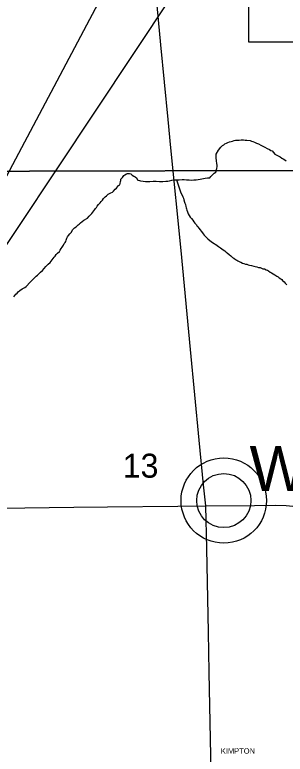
# Model space of a CAD drawing. Extents: x 10.6 to 44.6, y -2.6 to 23.4.
# Drawn here: x 17.431 to 17.902, y 17.784 to 19.074 of the extents above; entities that cross this region are included whole.
import ezdxf

# ---------------------------------------------------------------- set-up
doc = ezdxf.new("R2010")
doc.units = 0
for name, color, linetype in [('GM_X_Minor_River', 7, 'Continuous'), ('GM_X_Section', 7, 'Continuous'), ('GM_X_Section_Text', 7, 'Continuous'), ('GM_X_State_Route', 7, 'Continuous'), ('GM_X_Township_Subdivision_Text', 7, 'Continuous'), ('GM_X_Unincorporated', 7, 'Continuous'), ('GM_X_Unincorporated_Text', 7, 'Continuous'), ('GM_X_US_Route', 7, 'Continuous'), ('SH_Border', 7, 'Continuous')]:
    doc.layers.add(name, color=color, linetype=linetype)

msp = doc.modelspace()

# ---------------------------------------------------------------- linework, layer by layer
at = {"layer": 'GM_X_Minor_River'}
for points in [[(17.7427, 18.7858), (17.7469, 18.7862), (17.7503, 18.7867), (17.7537, 18.7871), (17.7625, 18.7888), (17.7663, 18.7893), (17.7689, 18.7894), (17.7708, 18.7898), (17.7723, 18.7917), (17.7756, 18.7952), (17.7782, 18.7979), (17.7809, 18.7995), (17.783, 18.806), (17.7833, 18.8094), (17.7833, 18.8117), (17.7828, 18.8144), (17.7824, 18.8193), (17.7815, 18.8246), (17.7818, 18.8269), (17.7817, 18.8307), (17.7854, 18.838), (17.7895, 18.843), (17.7924, 18.8457), (17.7947, 18.8473), (17.7969, 18.8489), (17.7996, 18.8501), (17.8022, 18.8513), (17.8049, 18.8521), (17.8075, 18.8529), (17.8098, 18.8537), (17.8132, 18.8545), (17.8154, 18.855), (17.8173, 18.8554), (17.8192, 18.8554), (17.8219, 18.8555), (17.8249, 18.8556), (17.8291, 18.8556), (17.8322, 18.8553), (17.8348, 18.8554), (17.8409, 18.8544), (17.8432, 18.8537), (17.8455, 18.853), (17.8486, 18.8515), (17.8517, 18.8501), (17.8551, 18.8486), (17.8594, 18.8464), (17.8628, 18.8446), (17.8663, 18.8428), (17.8702, 18.8406), (17.8744, 18.8388), (17.8771, 18.8373), (17.879, 18.8366), (17.8837, 18.8306), (17.8894, 18.8277), (17.8929, 18.8259), (17.896, 18.824), (17.8983, 18.8226), (17.901, 18.8207), (17.9037, 18.8193)], [(17.4723, 18.6214), (17.4757, 18.6249), (17.4791, 18.628), (17.482, 18.6315), (17.485, 18.635), (17.4887, 18.6389), (17.4921, 18.6416), (17.4943, 18.6439), (17.4958, 18.6462), (17.4976, 18.6486), (17.4995, 18.6509), (17.501, 18.6528), (17.5028, 18.6559), (17.5054, 18.6579), (17.5084, 18.661), (17.5095, 18.6633), (17.5113, 18.666), (17.5132, 18.6687), (17.5158, 18.6721), (17.5169, 18.6748), (17.5183, 18.6768), (17.5194, 18.6787), (17.5205, 18.681), (17.5216, 18.684), (17.5227, 18.6864), (17.5242, 18.6887), (17.5264, 18.6918), (17.529, 18.6941), (17.5316, 18.6995), (17.5349, 18.7022), (17.5375, 18.7042), (17.5394, 18.7057), (17.5413, 18.7073), (17.5431, 18.7088), (17.5454, 18.7108), (17.548, 18.7131), (17.551, 18.7155), (17.5574, 18.719), (17.5604, 18.7225), (17.5626, 18.7252), (17.5648, 18.7275), (17.5667, 18.7299), (17.5685, 18.7318), (17.5704, 18.7341), (17.5715, 18.7361), (17.573, 18.738), (17.5744, 18.7399), (17.5763, 18.743), (17.5793, 18.7457), (17.5815, 18.7484), (17.5837, 18.7508), (17.5852, 18.7535), (17.5882, 18.7562), (17.5904, 18.7581), (17.5934, 18.7612), (17.5979, 18.7632), (17.6009, 18.7648), (17.6028, 18.766), (17.6058, 18.7695), (17.608, 18.7718), (17.6098, 18.7741), (17.6117, 18.7761), (17.6136, 18.7776), (17.6143, 18.7799), (17.615, 18.783), (17.6157, 18.7849), (17.6157, 18.7872), (17.6186, 18.7903), (17.6209, 18.7934), (17.6227, 18.7946), (17.6253, 18.7965), (17.6272, 18.7969), (17.6307, 18.797), (17.633, 18.7967), (17.6353, 18.7944), (17.638, 18.7926), (17.6407, 18.7911), (17.6434, 18.7889), (17.6442, 18.7863), (17.6496, 18.7845), (17.6542, 18.7835), (17.6583, 18.7832), (17.6621, 18.7832), (17.666, 18.7833), (17.672, 18.7835), (17.677, 18.7836), (17.6831, 18.7833), (17.6888, 18.7831), (17.6941, 18.7836), (17.6975, 18.784), (17.7005, 18.7845), (17.7043, 18.7853), (17.7085, 18.7858), (17.7127, 18.7862), (17.7172, 18.7863), (17.7222, 18.7864), (17.726, 18.7865), (17.7298, 18.7862), (17.7344, 18.7859), (17.7386, 18.7857), (17.7427, 18.7858)], [(17.7127, 18.7862), (17.7192, 18.7651), (17.7236, 18.7561), (17.7244, 18.7542), (17.7252, 18.7512), (17.7264, 18.747), (17.7272, 18.7451), (17.728, 18.7432), (17.7285, 18.7398), (17.7293, 18.7372), (17.7297, 18.7353), (17.7305, 18.733), (17.7317, 18.7304), (17.733, 18.727), (17.7345, 18.724), (17.7365, 18.721), (17.7385, 18.7184), (17.7408, 18.7158), (17.7428, 18.7128), (17.7443, 18.7105), (17.7471, 18.7076), (17.7482, 18.7057), (17.7498, 18.7038), (17.7514, 18.7019), (17.7537, 18.699), (17.7557, 18.6963), (17.7576, 18.6937), (17.7588, 18.6918), (17.7608, 18.6896), (17.7623, 18.6877), (17.7643, 18.6859), (17.767, 18.6833), (17.7732, 18.6781), (17.7763, 18.6759), (17.7786, 18.6744), (17.7809, 18.6733), (17.7832, 18.6715), (17.7859, 18.6696), (17.789, 18.6674), (17.7913, 18.6656), (17.7936, 18.6641), (17.7967, 18.6623), (17.799, 18.66), (17.801, 18.6586), (17.8041, 18.656), (17.8072, 18.6534), (17.8099, 18.6508), (17.8122, 18.6493), (17.8153, 18.6471), (17.8176, 18.646), (17.8195, 18.6449), (17.8226, 18.6431), (17.8245, 18.6423), (17.8272, 18.6409), (17.8299, 18.6402), (17.833, 18.6391), (17.8349, 18.6388), (17.8376, 18.6377), (17.8395, 18.6374), (17.8429, 18.6363), (17.8471, 18.6352), (17.8494, 18.6349), (17.8525, 18.6342), (17.8555, 18.6331), (17.8582, 18.6328), (17.8605, 18.6321), (17.8632, 18.631), (17.8659, 18.6307), (17.8686, 18.6292), (17.8709, 18.6282), (17.8728, 18.6271), (17.8759, 18.6248), (17.8782, 18.6237), (17.8809, 18.6219), (17.8836, 18.6201), (17.8871, 18.6179), (17.8894, 18.6168), (17.8913, 18.6153), (17.894, 18.6131), (17.8959, 18.612), (17.8971, 18.6101), (17.9002, 18.6079), (17.9018, 18.606), (17.9049, 18.603)], [(17.4291, 18.5821), (17.4309, 18.584), (17.4324, 18.5863), (17.4346, 18.5883), (17.4365, 18.5906), (17.4395, 18.593), (17.4436, 18.5961), (17.4481, 18.5981), (17.4504, 18.6), (17.4578, 18.6074), (17.46, 18.6097), (17.4626, 18.6125), (17.4653, 18.6152), (17.4679, 18.6179), (17.4701, 18.6195), (17.4723, 18.6214)]]:
    msp.add_lwpolyline(points, dxfattribs=at)
at = {"layer": 'GM_X_Section'}
msp.add_lwpolyline([(18.1592, 19.0263), (18.1646, 18.8031), (17.2198, 18.8008), (17.1955, 19.8385), (18.1394, 19.8405), (18.1454, 19.5913)], dxfattribs=at)
msp.add_lwpolyline([(17.2198, 18.8008), (18.1646, 18.8031), (18.1656, 18.7612), (18.1848, 17.6775), (17.2448, 17.6704)], close=True, dxfattribs=at)
at = {"layer": 'GM_X_State_Route'}
for points in [[(17.7636, 18.2173), (17.7596, 18.2541), (17.7522, 18.3316), (17.737, 18.4901), (17.7205, 18.663), (17.7028, 18.8418), (17.6978, 18.8915), (17.6854, 19.0216), (17.6687, 19.1967)], [(17.8012, 15.5267), (17.7999, 15.6245), (17.7994, 15.6969), (17.798, 15.8329), (17.7956, 16.0407), (17.7937, 16.2499), (17.7904, 16.4688), (17.788, 16.5964), (17.7861, 16.6856), (17.7836, 16.85), (17.7826, 16.9026), (17.7801, 17.0459), (17.7792, 17.124), (17.7789, 17.1502), (17.7773, 17.3034), (17.7765, 17.3624), (17.7744, 17.5784), (17.7731, 17.7202), (17.7723, 17.7811), (17.7695, 17.9272), (17.7683, 17.9968), (17.7654, 18.1426), (17.7636, 18.2173)]]:
    msp.add_lwpolyline(points, dxfattribs=at)
at = {"layer": 'GM_X_Unincorporated'}
for radius in [0.0744, 0.0472]:
    msp.add_circle((17.7949, 18.2264), radius, dxfattribs=at)
at = {"layer": 'GM_X_US_Route'}
for points in [[(17.2002, 18.2107), (17.2334, 18.2109), (17.5338, 18.2149), (17.5925, 18.2155)], [(17.5925, 18.2155), (17.7146, 18.2167), (17.7636, 18.2173)], [(17.7636, 18.2173), (17.8485, 18.2178), (17.8844, 18.2181), (17.9035, 18.2176), (17.9152, 18.2164), (17.9351, 18.2127), (17.9564, 18.2071), (18.0054, 18.1872), (18.0438, 18.1716), (18.1741, 18.1191), (18.2568, 18.0854), (18.4732, 17.9974), (18.5668, 17.9597), (18.6315, 17.9333)]]:
    msp.add_lwpolyline(points, dxfattribs=at)
at = {"layer": 'SH_Border'}
for points in [[(17.8388, 19.5913), (17.1022, 18.1998), (17.8388, 19.3088)], [(17.8388, 19.5913), (19.6562, 19.5913), (19.6562, 19.0263), (17.8388, 19.0263)]]:
    msp.add_lwpolyline(points, close=True, dxfattribs=at)

# ---------------------------------------------------------------- texts
at = {"layer": 'GM_X_Section_Text'}
msp.add_text('13', height=0.04186, rotation=0, dxfattribs=at).set_placement((17.6188, 18.2663))
at = {"layer": 'GM_X_Township_Subdivision_Text'}
msp.add_text('KIMPTON', height=0.00947, rotation=0, dxfattribs=at).set_placement((17.7897, 17.7847))
at = {"layer": 'GM_X_Unincorporated_Text'}
msp.add_text('Welshfield', height=0.07898, rotation=0, dxfattribs=at).set_placement((17.8397, 18.2428))

doc.saveas('drawing.dxf')
